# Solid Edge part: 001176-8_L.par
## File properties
Last saved by: morva
Revision: 82
Accuracy: 0.990
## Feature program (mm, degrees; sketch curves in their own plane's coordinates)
body "unnamed Body 1"
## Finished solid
Body 1: solid body, 28 faces, 73 edges, 47 vertices.
  Faces by surface: cylinder 12, cone 8, plane 8
  Edges by curve: circle 33, line 29, curve on surface 7, spline 4
Bounding box of the edges (mm): 18.652 x 11.488 x 27.580, from (512.3104, 407.1762, -60.8976) to (530.9624, 418.6643, -33.3175).
Cylindrical faces by radius (mm): R2.5 x3, R3 x3, R3.5 x3, R4.5 x3
Conical faces (half-angle, radius in mm at the cone's reference point): 4.514 deg R5.75 x5, 45 deg R3.5 x3
Planar faces by outward normal: oblique 8
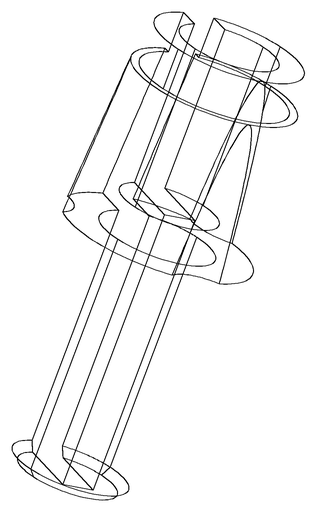
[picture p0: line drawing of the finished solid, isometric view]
